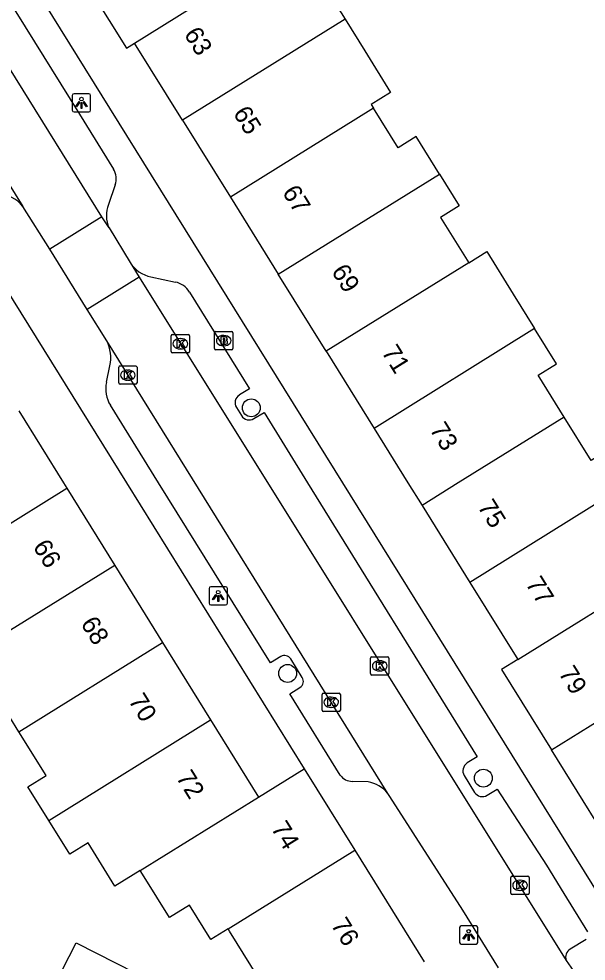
# Model space of a CAD drawing. Extents: x 159280 to 160375, y 384531 to 385872.
# Drawn here: x 160021.3 to 160052.3, y 384973.9 to 385025.3 of the extents above; entities that cross this region are included whole.
import ezdxf

# ---------------------------------------------------------------- set-up
doc = ezdxf.new("R2010")
doc.units = 0
for name, color, linetype in [('IMGEO_Boom', 7, 'Continuous'), ('IMGEO_Brandkraan', 7, 'Continuous'), ('IMGEO_Kolk', 7, 'Continuous'), ('IMGEO_Lichtpunt', 7, 'Continuous'), ('IMGEO_Pand', 7, 'Continuous'), ('IMGEO_Pand_nummerreeks', 7, 'Continuous'), ('IMGEO_Rijbaan_lokaal_open', 7, 'Continuous'), ('IMGEO_Voetpad_open', 7, 'Continuous')]:
    doc.layers.add(name, color=color, linetype=linetype)

msp = doc.modelspace()

# ---------------------------------------------------------------- linework, layer by layer
at = {"layer": 'IMGEO_Boom'}
for centre in [(160033.98, 385004.094), (160035.964, 384989.592), (160046.648, 384983.874)]:
    msp.add_circle(centre, 0.489, dxfattribs=at)
at = {"layer": 'IMGEO_Brandkraan'}
for p, q in [((160032.048, 385008.264), (160032.9, 385008.264)), ((160031.973, 385007.338), (160031.973, 385008.19)), ((160032.461, 385008.044), (160032.486, 385008.044)), ((160032.974, 385008.19), (160032.974, 385007.338)), ((160032.9, 385007.264), (160032.048, 385007.264)), ((160032.484, 385007.484), (160032.459, 385007.484))]:
    msp.add_line(p, q, dxfattribs=at)
for points in [[(160032.048, 385008.264), (160032.9, 385008.264)], [(160031.973, 385007.338), (160031.973, 385008.19)], [(160032.321, 385007.964), (160032.321, 385007.564), (160032.534, 385007.564)], [(160032.552, 385007.964), (160032.321, 385007.964)], [(160032.5, 385007.883), (160032.446, 385007.883), (160032.446, 385007.807)], [(160032.446, 385007.807), (160032.499, 385007.807)], [(160032.508, 385007.731), (160032.446, 385007.731), (160032.446, 385007.65)], [(160032.974, 385008.19), (160032.974, 385007.338)], [(160032.9, 385007.264), (160032.048, 385007.264)], [(160032.446, 385007.65), (160032.508, 385007.65)]]:
    msp.add_lwpolyline(points, dxfattribs=at)
for centre, radius, start, end in [((160032.05, 385008.188), 0.0765, 91.552, 178.448), ((160032.05, 385008.188), 0.0765, 91.552, 178.448), ((160032.898, 385008.188), 0.0765, 1.552, 88.448), ((160032.898, 385008.188), 0.0765, 1.552, 88.448), ((160032.501, 385007.845), 0.0379, 267.8285, 90.9355), ((160032.509, 385007.69), 0.0404, 269.8759, 90.5077), ((160032.556, 385007.819), 0.145, 59.4692, 91.5367), ((160032.581, 385007.866), 0.0922, 285.5137, 58.1501), ((160032.586, 385007.674), 0.105, 301.3115, 78.989), ((160032.05, 385007.34), 0.0765, 181.552, 268.448), ((160032.05, 385007.34), 0.0765, 181.552, 268.448), ((160032.54, 385007.815), 0.251, 268.6676, 293.5347), ((160032.898, 385007.34), 0.0765, 271.552, 358.448), ((160032.898, 385007.34), 0.0765, 271.552, 358.448)]:
    msp.add_arc(centre, radius, start, end, dxfattribs=at)
for centre, major_axis, ratio, start_param, end_param in [((160032.46, 385007.764), (-0.387, 0.002), 0.722429, 4.712389, 7.853982), ((160032.485, 385007.764), (-0.39, 0.002), 0.717154, 1.570796, 4.712389)]:
    msp.add_ellipse(centre, major_axis=major_axis, ratio=ratio, start_param=start_param, end_param=end_param, dxfattribs=at)
at = {"layer": 'IMGEO_Kolk'}
for p, q in [((160029.605, 385007.167), (160029.605, 385008.019)), ((160029.68, 385008.093), (160030.532, 385008.093)), ((160030.093, 385007.873), (160030.118, 385007.873)), ((160030.606, 385008.019), (160030.606, 385007.167)), ((160030.116, 385007.313), (160030.091, 385007.313)), ((160030.532, 385007.093), (160029.68, 385007.093)), ((160026.74, 385005.453), (160026.74, 385006.305)), ((160026.815, 385006.379), (160027.667, 385006.379)), ((160027.228, 385006.159), (160027.253, 385006.159)), ((160027.741, 385006.305), (160027.741, 385005.453)), ((160027.667, 385005.379), (160026.815, 385005.379)), ((160027.251, 385005.599), (160027.226, 385005.599)), ((160040.49, 384989.58), (160040.49, 384990.432)), ((160040.565, 384990.506), (160041.417, 384990.506)), ((160040.978, 384990.286), (160041.003, 384990.286)), ((160041.491, 384990.432), (160041.491, 384989.58)), ((160041.001, 384989.726), (160040.976, 384989.726)), ((160041.417, 384989.506), (160040.565, 384989.506)), ((160037.842, 384987.591), (160037.842, 384988.443)), ((160037.917, 384988.517), (160038.769, 384988.517)), ((160038.33, 384988.297), (160038.355, 384988.297)), ((160038.843, 384988.443), (160038.843, 384987.591)), ((160038.353, 384987.737), (160038.328, 384987.737)), ((160038.769, 384987.517), (160037.917, 384987.517)), ((160048.149, 384977.598), (160048.149, 384978.45)), ((160048.224, 384978.524), (160049.076, 384978.524)), ((160049.15, 384978.45), (160049.15, 384977.598)), ((160048.637, 384978.304), (160048.662, 384978.304)), ((160049.076, 384977.524), (160048.224, 384977.524)), ((160048.66, 384977.744), (160048.635, 384977.744))]:
    msp.add_line(p, q, dxfattribs=at)
for points in [[(160029.605, 385007.167), (160029.605, 385008.019)], [(160029.68, 385008.093), (160030.532, 385008.093)], [(160029.926, 385007.793), (160030.049, 385007.793), (160030.049, 385007.642), (160030.179, 385007.793), (160030.343, 385007.793), (160030.197, 385007.642), (160030.35, 385007.393), (160030.198, 385007.393), (160030.113, 385007.557), (160030.049, 385007.49), (160030.049, 385007.393), (160029.926, 385007.393), (160029.926, 385007.793)], [(160030.606, 385008.019), (160030.606, 385007.167)], [(160030.532, 385007.093), (160029.68, 385007.093)], [(160026.74, 385005.453), (160026.74, 385006.305)], [(160026.815, 385006.379), (160027.667, 385006.379)], [(160027.741, 385006.305), (160027.741, 385005.453)], [(160027.061, 385006.079), (160027.184, 385006.079), (160027.184, 385005.928), (160027.314, 385006.079), (160027.478, 385006.079), (160027.332, 385005.928), (160027.485, 385005.679), (160027.333, 385005.679), (160027.248, 385005.843), (160027.184, 385005.776), (160027.184, 385005.679), (160027.061, 385005.679), (160027.061, 385006.079)], [(160027.667, 385005.379), (160026.815, 385005.379)], [(160040.49, 384989.58), (160040.49, 384990.432)], [(160040.565, 384990.506), (160041.417, 384990.506)], [(160040.811, 384990.206), (160040.934, 384990.206), (160040.934, 384990.055), (160041.064, 384990.206), (160041.228, 384990.206), (160041.082, 384990.055), (160041.235, 384989.806), (160041.083, 384989.806), (160040.998, 384989.97), (160040.934, 384989.903), (160040.934, 384989.806), (160040.811, 384989.806), (160040.811, 384990.206)], [(160041.491, 384990.432), (160041.491, 384989.58)], [(160041.417, 384989.506), (160040.565, 384989.506)], [(160037.842, 384987.591), (160037.842, 384988.443)], [(160037.917, 384988.517), (160038.769, 384988.517)], [(160038.163, 384988.217), (160038.286, 384988.217), (160038.286, 384988.066), (160038.416, 384988.217), (160038.58, 384988.217), (160038.434, 384988.066), (160038.587, 384987.817), (160038.435, 384987.817), (160038.35, 384987.981), (160038.286, 384987.914), (160038.286, 384987.817), (160038.163, 384987.817), (160038.163, 384988.217)], [(160038.843, 384988.443), (160038.843, 384987.591)], [(160038.769, 384987.517), (160037.917, 384987.517)], [(160048.149, 384977.598), (160048.149, 384978.45)], [(160048.224, 384978.524), (160049.076, 384978.524)], [(160049.15, 384978.45), (160049.15, 384977.598)], [(160048.47, 384978.224), (160048.593, 384978.224), (160048.593, 384978.073), (160048.723, 384978.224), (160048.887, 384978.224), (160048.741, 384978.073), (160048.894, 384977.824), (160048.742, 384977.824), (160048.657, 384977.988), (160048.593, 384977.921), (160048.593, 384977.824), (160048.47, 384977.824), (160048.47, 384978.224)], [(160049.076, 384977.524), (160048.224, 384977.524)]]:
    msp.add_lwpolyline(points, dxfattribs=at)
for centre, start, end in [((160029.682, 385008.017), 91.552, 178.448), ((160029.682, 385008.017), 91.552, 178.448), ((160030.53, 385008.017), 1.552, 88.448), ((160030.53, 385008.017), 1.552, 88.448), ((160029.682, 385007.169), 181.552, 268.448), ((160029.682, 385007.169), 181.552, 268.448), ((160030.53, 385007.169), 271.552, 358.448), ((160030.53, 385007.169), 271.552, 358.448), ((160026.817, 385006.303), 91.552, 178.448), ((160026.817, 385006.303), 91.552, 178.448), ((160027.665, 385006.303), 1.552, 88.448), ((160027.665, 385006.303), 1.552, 88.448), ((160026.817, 385005.455), 181.552, 268.448), ((160026.817, 385005.455), 181.552, 268.448), ((160027.665, 385005.455), 271.552, 358.448), ((160027.665, 385005.455), 271.552, 358.448), ((160040.567, 384990.43), 91.552, 178.448), ((160040.567, 384990.43), 91.552, 178.448), ((160041.415, 384990.43), 1.552, 88.448), ((160041.415, 384990.43), 1.552, 88.448), ((160040.567, 384989.582), 181.552, 268.448), ((160040.567, 384989.582), 181.552, 268.448), ((160041.415, 384989.582), 271.552, 358.448), ((160041.415, 384989.582), 271.552, 358.448), ((160037.919, 384988.441), 91.552, 178.448), ((160037.919, 384988.441), 91.552, 178.448), ((160038.767, 384988.441), 1.552, 88.448), ((160038.767, 384988.441), 1.552, 88.448), ((160037.919, 384987.593), 181.552, 268.448), ((160037.919, 384987.593), 181.552, 268.448), ((160038.767, 384987.593), 271.552, 358.448), ((160038.767, 384987.593), 271.552, 358.448), ((160048.226, 384978.448), 91.552, 178.448), ((160048.226, 384978.448), 91.552, 178.448), ((160049.074, 384978.448), 1.552, 88.448), ((160049.074, 384978.448), 1.552, 88.448), ((160048.226, 384977.6), 181.552, 268.448), ((160048.226, 384977.6), 181.552, 268.448), ((160049.074, 384977.6), 271.552, 358.448), ((160049.074, 384977.6), 271.552, 358.448)]:
    msp.add_arc(centre, 0.0765, start, end, dxfattribs=at)
for centre, major_axis, ratio, start_param, end_param in [((160030.092, 385007.593), (-0.387, 0.002), 0.722429, 4.712389, 7.853982), ((160030.117, 385007.593), (-0.39, 0.002), 0.717154, 1.570796, 4.712389), ((160027.227, 385005.879), (-0.387, 0.002), 0.722429, 4.712389, 7.853982), ((160027.252, 385005.879), (-0.39, 0.002), 0.717154, 1.570796, 4.712389), ((160040.977, 384990.006), (-0.387, 0.002), 0.722429, 4.712389, 7.853982), ((160041.002, 384990.006), (-0.39, 0.002), 0.717154, 1.570796, 4.712389), ((160038.329, 384988.017), (-0.387, 0.002), 0.722429, 4.712389, 7.853982), ((160038.354, 384988.017), (-0.39, 0.002), 0.717154, 1.570796, 4.712389), ((160048.636, 384978.024), (-0.387, 0.002), 0.722429, 4.712389, 7.853982), ((160048.661, 384978.024), (-0.39, 0.002), 0.717154, 1.570796, 4.712389)]:
    msp.add_ellipse(centre, major_axis=major_axis, ratio=ratio, start_param=start_param, end_param=end_param, dxfattribs=at)
at = {"layer": 'IMGEO_Lichtpunt'}
for p, q in [((160024.208, 385021.151), (160024.208, 385020.344)), ((160024.208, 385021.151), (160024.208, 385020.344)), ((160025.11, 385021.246), (160024.302, 385021.246)), ((160025.11, 385021.246), (160024.302, 385021.246)), ((160025.204, 385020.344), (160025.204, 385021.151)), ((160025.204, 385020.344), (160025.204, 385021.151)), ((160024.302, 385020.25), (160025.11, 385020.25)), ((160024.302, 385020.25), (160025.11, 385020.25)), ((160032.58, 384994.326), (160031.772, 384994.326)), ((160032.58, 384994.326), (160031.772, 384994.326)), ((160031.678, 384994.231), (160031.678, 384993.424)), ((160031.678, 384994.231), (160031.678, 384993.424)), ((160032.674, 384993.424), (160032.674, 384994.231)), ((160032.674, 384993.424), (160032.674, 384994.231)), ((160031.772, 384993.33), (160032.58, 384993.33)), ((160031.772, 384993.33), (160032.58, 384993.33)), ((160046.251, 384975.808), (160045.443, 384975.808)), ((160046.251, 384975.808), (160045.443, 384975.808)), ((160045.349, 384975.713), (160045.349, 384974.906)), ((160045.349, 384975.713), (160045.349, 384974.906)), ((160046.345, 384974.906), (160046.345, 384975.713)), ((160046.345, 384974.906), (160046.345, 384975.713)), ((160045.443, 384974.812), (160046.251, 384974.812)), ((160045.443, 384974.812), (160046.251, 384974.812))]:
    msp.add_line(p, q, dxfattribs=at)
for points in [[(160024.582, 385020.815), (160024.621, 385020.787), (160024.433, 385020.525), (160024.395, 385020.552), (160024.582, 385020.815)], [(160024.684, 385020.767), (160024.731, 385020.767), (160024.731, 385020.445), (160024.684, 385020.445), (160024.684, 385020.767)], [(160024.794, 385020.787), (160024.832, 385020.814), (160025.019, 385020.552), (160024.98, 385020.524), (160024.794, 385020.787)], [(160032.052, 384993.895), (160032.091, 384993.867), (160031.903, 384993.605), (160031.865, 384993.632), (160032.052, 384993.895)], [(160032.154, 384993.847), (160032.201, 384993.847), (160032.201, 384993.525), (160032.154, 384993.525), (160032.154, 384993.847)], [(160032.264, 384993.867), (160032.302, 384993.894), (160032.489, 384993.632), (160032.45, 384993.604), (160032.264, 384993.867)], [(160045.723, 384975.377), (160045.762, 384975.349), (160045.574, 384975.087), (160045.536, 384975.114), (160045.723, 384975.377)], [(160045.825, 384975.329), (160045.872, 384975.329), (160045.872, 384975.007), (160045.825, 384975.007), (160045.825, 384975.329)], [(160045.935, 384975.349), (160045.973, 384975.376), (160046.16, 384975.114), (160046.121, 384975.086), (160045.935, 384975.349)]]:
    msp.add_lwpolyline(points, dxfattribs=at)
for centre in [(160024.707, 385020.949), (160032.177, 384994.029), (160045.848, 384975.511)]:
    msp.add_circle(centre, 0.0994, dxfattribs=at)
for centre, start, end in [((160024.302, 385021.151), 90, 180), ((160024.302, 385021.151), 90, 180), ((160025.11, 385021.151), 0, 90), ((160025.11, 385021.151), 0, 90), ((160024.302, 385020.344), 180, 270), ((160024.302, 385020.344), 180, 270), ((160025.11, 385020.344), 270, 0), ((160025.11, 385020.344), 270, 360), ((160031.772, 384994.231), 90, 180), ((160031.772, 384994.231), 90, 180), ((160032.58, 384994.231), 0, 90), ((160032.58, 384994.231), 0, 90), ((160031.772, 384993.424), 180, 270), ((160031.772, 384993.424), 180, 270), ((160032.58, 384993.424), 270, 0), ((160032.58, 384993.424), 270, 360), ((160045.443, 384975.713), 90, 180), ((160045.443, 384975.713), 90, 180), ((160046.251, 384975.713), 0, 90), ((160046.251, 384975.713), 0, 90), ((160045.443, 384974.906), 180, 270), ((160045.443, 384974.906), 180, 270), ((160046.251, 384974.906), 270, 0), ((160046.251, 384974.906), 270, 360)]:
    msp.add_arc(centre, 0.0946, start, end, dxfattribs=at)
at = {"layer": 'IMGEO_Pand'}
for points in [[(160027.609, 385024), (160036.471, 385029.532)], [(160036.471, 385029.532), (160037.792, 385027.407), (160039.096, 385025.31)], [(160024.324, 385028.285), (160027.161, 385023.724), (160027.609, 385024)], [(160039.096, 385025.31), (160030.224, 385019.795)], [(160039.096, 385025.31), (160040.172, 385023.579), (160041.584, 385021.308), (160040.528, 385020.652), (160040.654, 385020.449)], [(160030.224, 385019.795), (160027.609, 385024)], [(160040.654, 385020.449), (160032.84, 385015.589)], [(160044.255, 385016.855), (160042.978, 385018.908), (160041.993, 385018.296), (160040.654, 385020.449)], [(160030.224, 385019.795), (160032.84, 385015.589)], [(160035.455, 385011.384), (160044.255, 385016.855)], [(160044.255, 385016.855), (160045.331, 385015.124), (160044.309, 385014.488), (160045.847, 385012.014)], [(160032.84, 385015.589), (160035.455, 385011.384)], [(160045.847, 385012.014), (160046.837, 385012.63), (160048.279, 385010.292), (160049.444, 385008.42)], [(160045.847, 385012.014), (160038.07, 385007.179)], [(160038.07, 385007.179), (160035.455, 385011.384)], [(160049.444, 385008.42), (160040.685, 385002.973)], [(160051.06, 385003.593), (160049.638, 385005.88), (160050.637, 385006.502), (160049.444, 385008.42)], [(160038.07, 385007.179), (160040.685, 385002.973)], [(160021.288, 385003.926), (160023.725, 385000), (160023.906, 384999.708)], [(160051.06, 385003.593), (160045.282, 385000), (160043.3, 384998.768)], [(160054.648, 385000), (160053.51, 385001.83), (160052.534, 385001.223), (160051.06, 385003.593)], [(160040.685, 385002.973), (160042.534, 385000), (160043.3, 384998.768)], [(160054.648, 385000), (160045.915, 384994.563)], [(160016.058, 384994.838), (160023.906, 384999.708)], [(160023.906, 384999.708), (160026.523, 384995.491)], [(160043.3, 384998.768), (160045.915, 384994.563)], [(160026.523, 384995.491), (160017.7, 384990.016)], [(160026.523, 384995.491), (160029.14, 384991.273)], [(160048.531, 384990.356), (160056.273, 384995.155)], [(160045.915, 384994.563), (160048.531, 384990.356)], [(160021.291, 384986.401), (160029.14, 384991.273)], [(160029.14, 384991.273), (160031.758, 384987.056)], [(160048.531, 384990.356), (160047.639, 384989.802), (160050.368, 384985.414)], [(160050.368, 384985.414), (160058.277, 384990.333)], [(160021.291, 384986.401), (160019.8, 384988.805), (160018.827, 384988.201), (160017.7, 384990.016)], [(160022.918, 384981.57), (160031.758, 384987.056)], [(160031.758, 384987.056), (160034.374, 384982.839)], [(160022.918, 384981.57), (160021.785, 384983.395), (160022.775, 384984.01), (160021.291, 384986.401)], [(160061.912, 384986.443), (160061.028, 384985.838), (160057.422, 384983.54), (160053.175, 384980.899), (160050.368, 384985.414)], [(160034.374, 384982.839), (160036.87, 384984.386)], [(160036.87, 384984.386), (160039.627, 384979.943)], [(160027.921, 384978.834), (160034.374, 384982.839)], [(160027.921, 384978.834), (160026.536, 384977.974), (160025.066, 384980.342), (160024.065, 384979.721), (160022.918, 384981.57)], [(160032.709, 384975.649), (160039.627, 384979.943)], [(160039.627, 384979.943), (160043.41, 384973.848)], [(160032.709, 384975.649), (160031.767, 384975.064), (160030.604, 384976.938), (160029.517, 384976.263), (160028.139, 384978.482), (160027.921, 384978.834)], [(160036.189, 384969.356), (160035.971, 384969.707), (160036.278, 384969.898), (160032.791, 384975.516), (160032.709, 384975.649)], [(160023.26, 384972.606), (160024.412, 384974.881), (160027.678, 384973.228), (160026.527, 384970.953)]]:
    msp.add_lwpolyline(points, dxfattribs=at)
at = {"layer": 'IMGEO_Rijbaan_lokaal_open'}
for points in [[(160025.818, 385014.518), (159990.522, 385071.361)], [(159987.649, 385069.578), (160021.503, 385015.093)], [(160022.974, 385012.749), (160021.503, 385015.093)], [(160025.818, 385014.518), (160022.974, 385012.749)], [(160026.212, 385013.913), (160025.818, 385014.518)], [(160026.212, 385013.913), (160027.358, 385012.029)], [(160025.016, 385009.463), (160022.974, 385012.749)], [(160027.358, 385012.029), (160027.858, 385011.23)], [(160027.858, 385011.23), (160025.016, 385009.463)], [(160027.858, 385011.23), (160051.175, 384973.916)], [(160026.084, 385007.744), (160025.016, 385009.463)], [(160041.435, 384983.037), (160026.084, 385007.744)], [(160047.481, 384973.51), (160045.525, 384976.659), (160041.541, 384982.866), (160041.435, 384983.037)], [(160051.175, 384973.916), (160051.804, 384973.014)]]:
    msp.add_lwpolyline(points, dxfattribs=at)
at = {"layer": 'IMGEO_Voetpad_open'}
for points in [[(160017.589, 385030.171), (160018.139, 385030.511), (160024.594, 385020.132), (160026.452, 385017.13)], [(160053.932, 384975.941), (160038.976, 385000), (160022.21, 385026.971)], [(160013.107, 385022.609), (160027.163, 385000), (160036.87, 384984.386)], [(160026.548, 385016.278), (160026.176, 385015.198)], [(160028.5, 385011.243), (160029.835, 385010.961)], [(160030.607, 385010.418), (160033.877, 385005.135), (160033.329, 385004.795)], [(160026.069, 385005.486), (160026.264, 385006.392)], [(160035.588, 384990.509), (160035.029, 384990.162), (160028.916, 385000), (160026.287, 385004.231)], [(160033.167, 385004.107), (160033.439, 385003.667)], [(160034.127, 385003.505), (160034.675, 385003.845), (160037.055, 385000), (160046.315, 384985.041), (160045.767, 384984.702)], [(160036.763, 384989.376), (160036.139, 384990.381)], [(160038.836, 384984.035), (160036.076, 384988.478), (160036.635, 384988.825)], [(160040.355, 384983.674), (160039.497, 384983.698)], [(160045.605, 384984.014), (160046.171, 384983.099)], [(160046.86, 384982.937), (160047.407, 384983.276), (160050.099, 384979.114), (160051.035, 384977.568), (160052.331, 384975.491)], [(160052.26, 384975.063), (160051.392, 384974.54)]]:
    msp.add_lwpolyline(points, dxfattribs=at)
for centre, radius, start, end in [((160025.603, 385016.603), 0.999, 341.0244, 31.8331), ((160020.052, 385013.951), 1.846, 38.209, 86.5949), ((160027.783, 385014.6), 1.714, 159.5857, 203.6238), ((160028.846, 385012.968), 1.759, 212.2595, 258.6639), ((160029.58, 385009.778), 1.21, 31.9167, 77.8406), ((160024.33, 385006.822), 1.981, 347.451, 27.716), ((160027.73, 385005.128), 1.699, 167.8405, 211.868), ((160033.59, 385004.37), 0.498, 121.5843, 211.9161), ((160033.864, 385003.932), 0.501, 211.9171, 301.5833), ((160035.799, 384990.169), 0.4, 31.9617, 121.8821), ((160036.423, 384989.165), 0.4, 301.9617, 31.8821), ((160046.032, 384984.277), 0.501, 121.9171, 211.5833), ((160039.484, 384984.489), 0.791, 215.0153, 270.9566), ((160039.997, 384981.833), 1.875, 39.9347, 78.9998), ((160046.597, 384983.365), 0.502, 211.9595, 301.578), ((160051.656, 384974.098), 0.515, 120.8909, 200.7582)]:
    msp.add_arc(centre, radius, start, end, dxfattribs=at)

# ---------------------------------------------------------------- texts
at = {"layer": 'IMGEO_Pand_nummerreeks'}
for s, rotation, p in [('63', 301.8648, (160030.275, 385024.496)), ('65', 301.862, (160032.957, 385020.18)), ('67', 301.8648, (160035.641, 385015.864)), ('69', 301.8648, (160038.323, 385011.548)), ('71', 301.862, (160041.065, 385007.137)), ('73', 301.8648, (160043.689, 385002.917)), ('75', 301.8834, (160046.309, 384998.697)), ('66', 301.8226, (160022.027, 384996.516)), ('77', 301.8834, (160048.926, 384994.491)), ('68', 301.8226, (160024.635, 384992.312)), ('79', 301.8739, (160050.727, 384989.609)), ('70', 301.8226, (160027.243, 384988.11)), ('72', 301.8219, (160029.847, 384983.914)), ('74', 301.8219, (160035.027, 384981.136)), ('76', 301.8219, (160038.296, 384975.868))]:
    msp.add_text(s, height=1, rotation=rotation, dxfattribs=at).set_placement(p)

doc.saveas('drawing.dxf')
